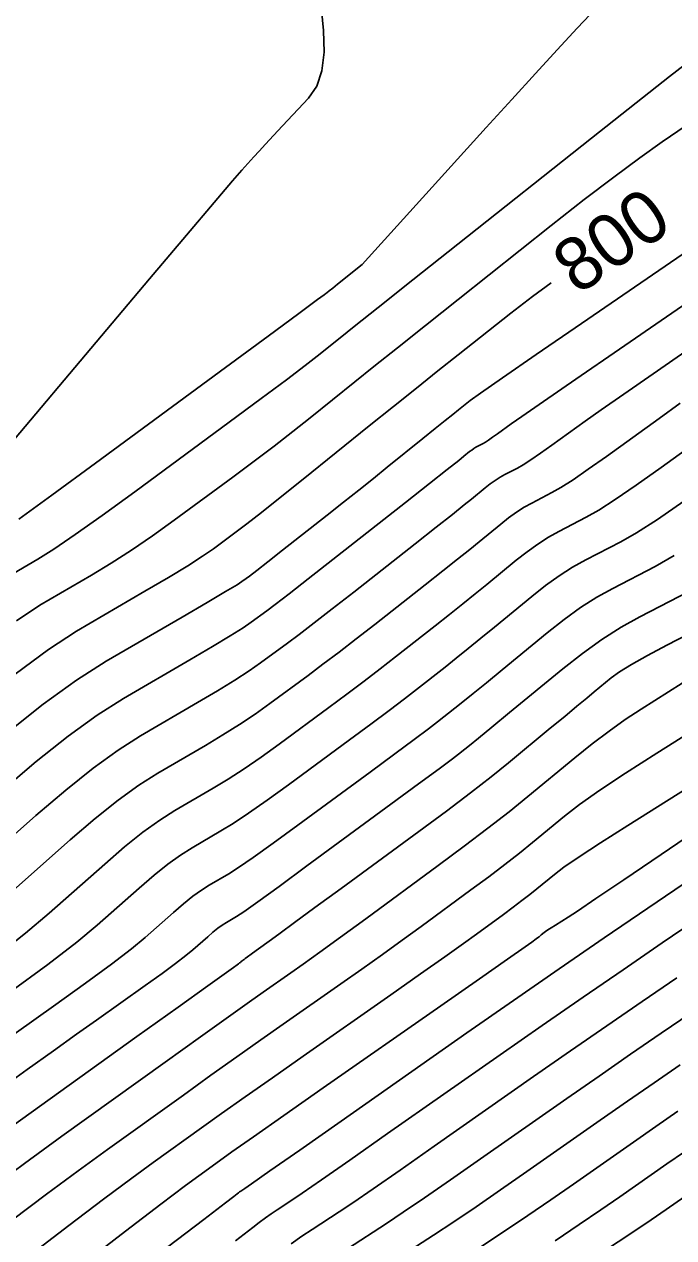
# Model space of a CAD drawing. Extents: x 2079879 to 2092887, y 778083 to 784051.
# Drawn here: x 2084488.3 to 2084522.6, y 781189.1 to 781253.2 of the extents above; entities that cross this region are included whole.
import ezdxf

# ---------------------------------------------------------------- set-up
doc = ezdxf.new("R2010")
doc.units = 0
doc.layers.add('DT_X_Contour_Major', color=7, linetype='Continuous')
doc.layers.add('DT_X_Contour_Minor', color=7, linetype='Continuous')

msp = doc.modelspace()

# ---------------------------------------------------------------- linework, layer by layer
at = {"layer": 'DT_X_Contour_Major'}
for points in [[(2084516.077, 781239.584), (2084515.094, 781238.859), (2084513.948, 781237.976), (2084511.182, 781235.779), (2084510.11, 781234.927), (2084508.97, 781234.015), (2084507.762, 781233.046), (2084506.485, 781232.018), (2084502.99, 781229.198), (2084501.786, 781228.231), (2084500.797, 781227.445), (2084500.022, 781226.84), (2084499.462, 781226.415), (2084498.252, 781225.525), (2084497.686, 781225.134), (2084496.895, 781224.629), (2084495.88, 781224.01), (2084494.639, 781223.278), (2084491.031, 781221.174), (2084489.542, 781220.213), (2084487.782, 781218.909)], [(2084525.697, 781232.565), (2084521.887, 781229.816), (2084520.569, 781228.879), (2084519.471, 781228.129), (2084518.596, 781227.566), (2084517.941, 781227.191), (2084516.49, 781226.44), (2084515.942, 781226.133), (2084515.383, 781225.778), (2084514.816, 781225.373), (2084514.239, 781224.918), (2084512.688, 781223.64), (2084512.081, 781223.144), (2084511.424, 781222.614), (2084510.717, 781222.05), (2084509.96, 781221.452), (2084507.873, 781219.811), (2084507.066, 781219.183), (2084506.209, 781218.527), (2084505.301, 781217.845), (2084504.343, 781217.135), (2084501.722, 781215.207), (2084500.767, 781214.519), (2084499.869, 781213.901), (2084499.027, 781213.354), (2084498.241, 781212.877), (2084496.221, 781211.699), (2084495.421, 781211.191), (2084494.536, 781210.55), (2084493.567, 781209.777), (2084492.513, 781208.871), (2084489.589, 781206.279), (2084488.336, 781205.22), (2084486.77, 781203.987)], [(2084561.451, 781220.438), (2084560.893, 781220.058), (2084559.657, 781219.199), (2084558.481, 781218.364), (2084555.427, 781216.17), (2084553.986, 781215.144), (2084551.955, 781213.712), (2084549.333, 781211.873), (2084546.121, 781209.628), (2084536.769, 781203.099), (2084533.593, 781200.884), (2084531.08, 781199.136), (2084529.231, 781197.855), (2084528.045, 781197.041), (2084525.767, 781195.493), (2084524.903, 781194.904), (2084524.02, 781194.297), (2084523.117, 781193.671), (2084522.196, 781193.027), (2084519.711, 781191.285), (2084518.71, 781190.592), (2084517.569, 781189.82), (2084516.289, 781188.969)], [(2084522.999, 781218.42), (2084520.828, 781217.052), (2084519.999, 781216.507), (2084519.142, 781215.898), (2084518.255, 781215.225), (2084517.34, 781214.488), (2084514.859, 781212.437), (2084513.866, 781211.632), (2084512.746, 781210.756), (2084511.499, 781209.809), (2084510.126, 781208.791), (2084506.296, 781205.981), (2084504.971, 781205.012), (2084503.869, 781204.211), (2084502.991, 781203.578), (2084502.335, 781203.113), (2084500.886, 781202.099), (2084500.155, 781201.583), (2084499.048, 781200.794), (2084497.567, 781199.734), (2084495.71, 781198.402), (2084490.259, 781194.487), (2084488.275, 781193.051), (2084486.409, 781191.681)], [(2084527.403, 781208.403), (2084521.95, 781204.698), (2084519.881, 781203.287), (2084517.767, 781201.833), (2084515.606, 781200.335), (2084513.399, 781198.793), (2084507.452, 781194.624), (2084505.464, 781193.231), (2084503.959, 781192.182), (2084502.938, 781191.475), (2084502.4, 781191.111), (2084501.611, 781190.597), (2084501.309, 781190.394), (2084500.995, 781190.173), (2084500.669, 781189.932), (2084500.332, 781189.672), (2084499.417, 781188.953)]]:
    msp.add_lwpolyline(points, dxfattribs=at)
at = {"layer": 'DT_X_Contour_Minor'}
for points in [[(2084503.748, 781256.219), (2084504.065, 781252.913), (2084504.105, 781251.76), (2084503.986, 781250.779), (2084503.709, 781249.97), (2084503.274, 781249.335), (2084501.903, 781247.869), (2084501.423, 781247.355), (2084501.011, 781246.912), (2084500.668, 781246.54), (2084500.394, 781246.239), (2084499.753, 781245.53), (2084499.268, 781244.972), (2084498.294, 781243.829), (2084496.832, 781242.102), (2084494.881, 781239.79), (2084484.634, 781227.637)], [(2084520.143, 781255.889), (2084517.463, 781253.026), (2084516.409, 781251.892), (2084515.255, 781250.64), (2084514.002, 781249.268), (2084512.65, 781247.776), (2084506.107, 781240.538), (2084504.8, 781239.5), (2084504.551, 781239.303), (2084504.365, 781239.155), (2084504.242, 781239.057), (2084504.181, 781239.009), (2084504.104, 781238.946), (2084503.756, 781238.688), (2084502.772, 781237.962), (2084501.151, 781236.767), (2084498.893, 781235.104), (2084492.023, 781230.044), (2084489.725, 781228.357), (2084487.981, 781227.093)], [(2084523.502, 781251.382), (2084522.33, 781250.471), (2084520.568, 781249.084), (2084518.216, 781247.221), (2084511.156, 781241.617), (2084508.783, 781239.732), (2084506.957, 781238.281), (2084505.679, 781237.263), (2084504.949, 781236.678), (2084503.733, 781235.697), (2084503.1, 781235.203), (2084502.114, 781234.456), (2084500.775, 781233.458), (2084499.083, 781232.208), (2084494.1, 781228.537), (2084492.378, 781227.283), (2084490.952, 781226.272), (2084489.821, 781225.505), (2084488.985, 781224.981), (2084487.149, 781223.911)], [(2084524.869, 781249.022), (2084521.953, 781247.023), (2084520.766, 781246.184), (2084519.392, 781245.167), (2084517.831, 781243.972), (2084516.082, 781242.598), (2084511.169, 781238.698), (2084509.446, 781237.33), (2084507.964, 781236.148), (2084506.721, 781235.154), (2084505.717, 781234.348), (2084503.361, 781232.447), (2084502.443, 781231.717), (2084501.456, 781230.951), (2084500.399, 781230.149), (2084499.272, 781229.312), (2084496.176, 781227.031), (2084495.032, 781226.208), (2084493.924, 781225.45), (2084492.85, 781224.758), (2084491.812, 781224.13), (2084489.09, 781222.542), (2084487.858, 781221.721)], [(2084524.906, 781242.382), (2084517.691, 781237.434), (2084515.295, 781235.787), (2084513.516, 781234.558), (2084512.356, 781233.746), (2084511.815, 781233.353), (2084511.194, 781232.861), (2084510.902, 781232.628), (2084510.492, 781232.299), (2084509.963, 781231.873), (2084509.316, 781231.351), (2084507.431, 781229.831), (2084506.703, 781229.245), (2084505.93, 781228.629), (2084505.114, 781227.982), (2084504.254, 781227.304), (2084501.901, 781225.454), (2084501.119, 781224.84), (2084500.538, 781224.384), (2084500.156, 781224.086), (2084499.975, 781223.948), (2084499.759, 781223.789), (2084499.501, 781223.627), (2084498.888, 781223.262), (2084497.92, 781222.693), (2084496.598, 781221.921), (2084492.6, 781219.589), (2084491.017, 781218.583), (2084489.266, 781217.315), (2084487.347, 781215.784)], [(2084526.57, 781240.813), (2084519.686, 781236.072), (2084517.393, 781234.492), (2084515.677, 781233.307), (2084514.538, 781232.517), (2084513.976, 781232.122), (2084513.246, 781231.595), (2084512.993, 781231.416), (2084512.783, 781231.272), (2084512.615, 781231.164), (2084512.49, 781231.092), (2084512.212, 781230.948), (2084512.107, 781230.89), (2084512, 781230.822), (2084511.891, 781230.744), (2084511.781, 781230.657), (2084511.483, 781230.412), (2084511.206, 781230.19), (2084510.598, 781229.709), (2084509.658, 781228.969), (2084508.386, 781227.968), (2084504.554, 781224.955), (2084503.258, 781223.938), (2084502.245, 781223.148), (2084501.515, 781222.583), (2084501.067, 781222.244), (2084500.25, 781221.643), (2084499.817, 781221.35), (2084499.133, 781220.922), (2084498.197, 781220.359), (2084497.009, 781219.66), (2084493.505, 781217.616), (2084492.118, 781216.735), (2084490.583, 781215.624), (2084488.902, 781214.282), (2084487.073, 781212.711)], [(2084523.367, 781236.089), (2084521.462, 781234.775), (2084519.913, 781233.7), (2084518.72, 781232.865), (2084517.883, 781232.27), (2084516.126, 781231.002), (2084515.518, 781230.57), (2084515.013, 781230.224), (2084514.609, 781229.965), (2084514.307, 781229.792), (2084513.638, 781229.446), (2084513.385, 781229.304), (2084513.128, 781229.14), (2084512.866, 781228.954), (2084512.6, 781228.744), (2084511.885, 781228.155), (2084511.498, 781227.842), (2084510.873, 781227.344), (2084510.011, 781226.662), (2084508.911, 781225.796), (2084505.661, 781223.241), (2084504.528, 781222.353), (2084503.566, 781221.607), (2084502.777, 781221.003), (2084502.159, 781220.541), (2084500.74, 781219.498), (2084500.134, 781219.073), (2084499.378, 781218.582), (2084498.474, 781218.024), (2084497.42, 781217.399), (2084494.41, 781215.644), (2084493.219, 781214.887), (2084491.901, 781213.932), (2084490.457, 781212.78), (2084488.887, 781211.431), (2084484.531, 781207.569)], [(2084522.902, 781233.213), (2084521.79, 781232.417), (2084519.007, 781230.409), (2084518.043, 781229.724), (2084517.242, 781229.176), (2084516.602, 781228.765), (2084516.124, 781228.491), (2084515.064, 781227.943), (2084514.663, 781227.719), (2084514.256, 781227.459), (2084513.841, 781227.163), (2084513.419, 781226.831), (2084512.286, 781225.897), (2084511.789, 781225.493), (2084511.148, 781224.979), (2084510.364, 781224.356), (2084509.435, 781223.624), (2084506.767, 781221.526), (2084505.797, 781220.768), (2084504.887, 781220.067), (2084504.039, 781219.424), (2084503.251, 781218.838), (2084501.231, 781217.352), (2084500.451, 781216.796), (2084499.624, 781216.242), (2084498.75, 781215.689), (2084497.83, 781215.138), (2084495.316, 781213.671), (2084494.32, 781213.039), (2084493.219, 781212.241), (2084492.012, 781211.279), (2084490.7, 781210.151), (2084487.06, 781206.924)], [(2084523.094, 781228.033), (2084521.701, 781227.081), (2084520.589, 781226.367), (2084519.758, 781225.89), (2084517.916, 781224.937), (2084517.22, 781224.548), (2084516.511, 781224.096), (2084515.791, 781223.582), (2084515.058, 781223.005), (2084513.089, 781221.383), (2084512.372, 781220.795), (2084511.699, 781220.249), (2084511.07, 781219.743), (2084510.484, 781219.279), (2084508.98, 781218.097), (2084508.335, 781217.597), (2084507.53, 781216.987), (2084506.563, 781216.265), (2084505.435, 781215.432), (2084502.213, 781213.061), (2084501.084, 781212.242), (2084500.114, 781211.561), (2084499.303, 781211.019), (2084498.652, 781210.616), (2084497.126, 781209.727), (2084496.522, 781209.343), (2084495.854, 781208.859), (2084495.122, 781208.275), (2084494.326, 781207.591), (2084492.118, 781205.633), (2084491.052, 781204.749), (2084489.51, 781203.563), (2084487.491, 781202.076)], [(2084522.583, 781225.167), (2084521.575, 781224.59), (2084519.342, 781223.434), (2084518.498, 781222.963), (2084517.639, 781222.415), (2084516.766, 781221.792), (2084515.878, 781221.092), (2084513.49, 781219.126), (2084512.664, 781218.446), (2084511.975, 781217.883), (2084511.423, 781217.437), (2084511.008, 781217.107), (2084510.086, 781216.382), (2084509.605, 781216.012), (2084508.851, 781215.447), (2084507.825, 781214.686), (2084506.527, 781213.729), (2084502.703, 781210.916), (2084501.4, 781209.965), (2084500.359, 781209.221), (2084499.58, 781208.685), (2084499.062, 781208.356), (2084498.031, 781207.754), (2084497.623, 781207.495), (2084497.172, 781207.168), (2084496.677, 781206.774), (2084496.139, 781206.311), (2084494.647, 781204.988), (2084493.925, 781204.389), (2084492.878, 781203.585), (2084491.506, 781202.574), (2084489.808, 781201.357), (2084484.849, 781197.839)], [(2084523.392, 781223.289), (2084520.769, 781221.931), (2084519.776, 781221.377), (2084518.767, 781220.734), (2084517.74, 781220.001), (2084516.697, 781219.179), (2084513.892, 781216.868), (2084512.955, 781216.098), (2084512.25, 781215.518), (2084511.776, 781215.131), (2084511.533, 781214.935), (2084511.193, 781214.667), (2084510.874, 781214.427), (2084510.172, 781213.907), (2084509.087, 781213.106), (2084507.619, 781212.026), (2084503.194, 781208.771), (2084501.717, 781207.688), (2084500.604, 781206.881), (2084499.856, 781206.35), (2084499.473, 781206.095), (2084498.937, 781205.782), (2084498.724, 781205.647), (2084498.49, 781205.477), (2084498.232, 781205.272), (2084497.953, 781205.031), (2084497.176, 781204.343), (2084496.801, 781204.032), (2084496.256, 781203.613), (2084495.542, 781203.087), (2084494.659, 781202.455), (2084492.08, 781200.624), (2084491.028, 781199.876), (2084489.806, 781199.005), (2084488.416, 781198.009), (2084486.856, 781196.89)], [(2084525.209, 781221.989), (2084522.195, 781220.428), (2084521.163, 781219.881), (2084520.33, 781219.412), (2084519.696, 781219.019), (2084519.259, 781218.702), (2084518.36, 781217.961), (2084517.962, 781217.633), (2084517.441, 781217.203), (2084516.799, 781216.672), (2084516.034, 781216.04), (2084513.832, 781214.219), (2084512.917, 781213.48), (2084511.823, 781212.63), (2084510.552, 781211.668), (2084509.102, 781210.595), (2084504.998, 781207.585), (2084503.614, 781206.57), (2084502.54, 781205.781), (2084501.775, 781205.22), (2084501.319, 781204.885), (2084500.516, 781204.295), (2084500.251, 781204.1), (2084500.057, 781203.958), (2084499.935, 781203.87), (2084499.884, 781203.834), (2084499.842, 781203.81), (2084499.826, 781203.799), (2084499.807, 781203.786), (2084499.787, 781203.77), (2084499.766, 781203.752), (2084499.706, 781203.698), (2084499.676, 781203.674), (2084499.634, 781203.642), (2084499.579, 781203.601), (2084499.511, 781203.552), (2084499.311, 781203.41), (2084498.936, 781203.142), (2084497.962, 781202.442), (2084496.388, 781201.313), (2084494.216, 781199.752), (2084487.622, 781195.017)], [(2084526.471, 781217.754), (2084521.672, 781214.73), (2084520.017, 781213.672), (2084518.653, 781212.765), (2084517.58, 781212.01), (2084516.796, 781211.407), (2084515.095, 781210), (2084514.413, 781209.447), (2084513.645, 781208.847), (2084512.79, 781208.197), (2084511.848, 781207.499), (2084509.22, 781205.571), (2084508.215, 781204.839), (2084507.173, 781204.089), (2084506.093, 781203.32), (2084504.975, 781202.534), (2084501.942, 781200.412), (2084500.76, 781199.581), (2084499.486, 781198.68), (2084498.122, 781197.708), (2084496.667, 781196.665), (2084492.666, 781193.792), (2084491.108, 781192.66), (2084489.434, 781191.421), (2084487.645, 781190.073)], [(2084524.362, 781213.572), (2084520.124, 781210.901), (2084518.69, 781209.989), (2084517.567, 781209.255), (2084516.754, 781208.701), (2084516.253, 781208.325), (2084515.33, 781207.562), (2084514.961, 781207.263), (2084514.544, 781206.937), (2084514.08, 781206.585), (2084513.569, 781206.206), (2084512.144, 781205.16), (2084511.46, 781204.666), (2084510.477, 781203.967), (2084509.195, 781203.063), (2084507.614, 781201.955), (2084502.999, 781198.725), (2084501.365, 781197.58), (2084499.924, 781196.565), (2084498.678, 781195.682), (2084497.624, 781194.929), (2084495.072, 781193.097), (2084493.941, 781192.269), (2084492.459, 781191.16), (2084490.628, 781189.769), (2084488.446, 781188.098)], [(2084527.774, 781213.374), (2084521.887, 781209.375), (2084519.924, 781208.043), (2084518.451, 781207.047), (2084517.469, 781206.387), (2084516.975, 781206.063), (2084516.314, 781205.646), (2084516.09, 781205.504), (2084515.915, 781205.389), (2084515.788, 781205.303), (2084515.71, 781205.244), (2084515.565, 781205.125), (2084515.508, 781205.078), (2084515.443, 781205.027), (2084515.37, 781204.972), (2084515.291, 781204.913), (2084515.068, 781204.75), (2084514.705, 781204.493), (2084513.781, 781203.845), (2084512.297, 781202.806), (2084510.253, 781201.375), (2084504.055, 781197.039), (2084501.97, 781195.579), (2084500.363, 781194.451), (2084499.233, 781193.656), (2084498.581, 781193.193), (2084497.479, 781192.401), (2084496.774, 781191.877), (2084495.484, 781190.899), (2084493.611, 781189.466), (2084491.153, 781187.578)], [(2084527.275, 781210.675), (2084521.186, 781206.539), (2084518.877, 781204.964), (2084516.516, 781203.34), (2084514.104, 781201.667), (2084511.64, 781199.946), (2084505.001, 781195.291), (2084502.815, 781193.759), (2084501.237, 781192.654), (2084500.268, 781191.976), (2084499.906, 781191.726), (2084499.754, 781191.626), (2084499.695, 781191.587), (2084499.634, 781191.544), (2084499.571, 781191.497), (2084499.506, 781191.447), (2084499.329, 781191.308), (2084498.899, 781190.976), (2084497.741, 781190.086), (2084495.856, 781188.638)], [(2084522.713, 781202.857), (2084520.886, 781201.611), (2084519.017, 781200.326), (2084517.108, 781199.002), (2084515.158, 781197.64), (2084509.904, 781193.956), (2084508.113, 781192.704), (2084506.681, 781191.71), (2084505.608, 781190.974), (2084504.894, 781190.496), (2084503.467, 781189.568), (2084502.922, 781189.202), (2084502.355, 781188.802)], [(2084523.477, 781201.016), (2084521.89, 781199.934), (2084520.268, 781198.818), (2084518.611, 781197.669), (2084516.918, 781196.486), (2084512.356, 781193.288), (2084510.762, 781192.176), (2084509.403, 781191.237), (2084508.278, 781190.473), (2084507.387, 781189.882), (2084505.324, 781188.538)], [(2084522.894, 781198.257), (2084521.519, 781197.311), (2084520.113, 781196.336), (2084518.677, 781195.333), (2084514.808, 781192.62), (2084513.412, 781191.648), (2084512.125, 781190.765), (2084510.948, 781189.971), (2084509.881, 781189.267), (2084507.181, 781187.509)], [(2084522.769, 781195.804), (2084521.615, 781195.003), (2084520.436, 781194.18), (2084517.26, 781191.953), (2084516.061, 781191.12), (2084514.847, 781190.293), (2084513.618, 781189.47), (2084512.375, 781188.653)], [(2084523.955, 781191.873), (2084522.163, 781190.617), (2084521.359, 781190.064), (2084520.291, 781189.348), (2084518.959, 781188.468)]]:
    msp.add_lwpolyline(points, dxfattribs=at)

# ---------------------------------------------------------------- texts
at = {"layer": 'DT_X_Contour_Major'}
msp.add_text('800', height=2.8, rotation=34.86931, dxfattribs=at).set_placement((2084517.485, 781238.894))

doc.saveas('drawing.dxf')
